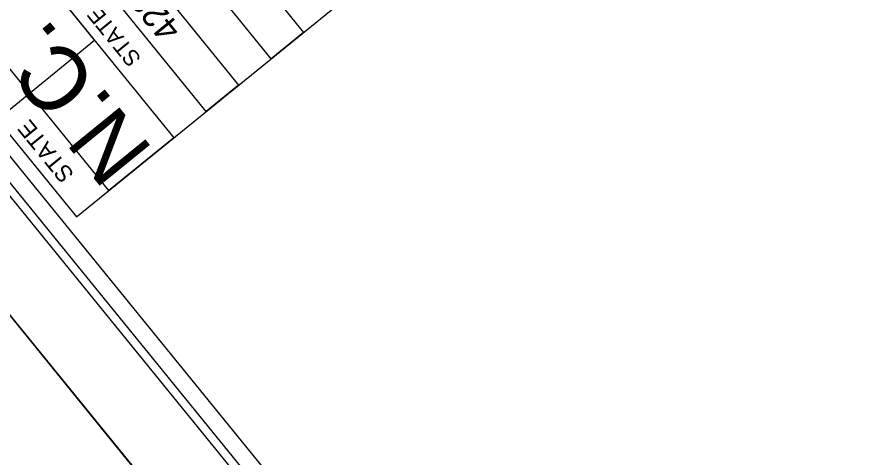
# Model space of a CAD drawing. Extents: x 2596486 to 2602076, y 851390 to 856110.
# Drawn here: x 2596823.3 to 2597258.5, y 853128.6 to 853352.8 of the extents above; entities that cross this region are included whole.
import ezdxf

# ---------------------------------------------------------------- set-up
doc = ezdxf.new("R2010")
doc.units = 0
for name, color, linetype in [('Sheet Cutting Line CELL', 7, 'Continuous'), ('Sheet Data Field CELL', 7, 'Continuous'), ('Sheet Plot Border Inside CELL', 7, 'Continuous'), ('Sheet Plot Border Outside CELL', 7, 'Continuous'), ('Sheet Title CELL', 7, 'Continuous')]:
    doc.layers.add(name, color=color, linetype=linetype)

msp = doc.modelspace()

# ---------------------------------------------------------------- linework, layer by layer
at = {"layer": 'Sheet Cutting Line CELL'}
msp.add_line((2598291.52, 851390.23), (2596485.91, 853611.8), dxfattribs=at)
at = {"layer": 'Sheet Plot Border Inside CELL'}
msp.add_lwpolyline([(2599699.12, 852562.74), (2597912.27, 854761.23), (2596520.36, 853629.94), (2598307.2, 851431.45)], close=True, dxfattribs=at)
at = {"layer": 'Sheet Plot Border Outside CELL'}
msp.add_lwpolyline([(2596485.91, 853611.8), (2598291.52, 851390.23), (2599742.65, 852569.65), (2597937.05, 854791.22)], close=True, dxfattribs=at)
at = {"layer": 'Sheet Title CELL'}
for points in [[(2596674.06, 853707.76), (2596968.92, 853344.98), (2596952.45, 853331.59), (2596657.57, 853694.36)], [(2596641.1, 853680.97), (2596935.96, 853318.18), (2596919.47, 853304.78), (2596624.61, 853667.57)], [(2596608.1, 853654.15), (2596902.96, 853291.37), (2596869.98, 853264.56), (2596575.12, 853627.35)], [(2596558.63, 853613.94), (2596853.5, 853251.17), (2597051.37, 853411.99), (2596953.12, 853532.91), (2596804.71, 853412.29), (2596862.77, 853340.85), (2596813.28, 853300.63)], [(2596547.83, 853603.01), (2598134.72, 851650.5)], [(2596559.8, 853601.75), (2598082.33, 851728.47)]]:
    msp.add_lwpolyline(points, dxfattribs=at)

# ---------------------------------------------------------------- texts
at = {"layer": 'Sheet Data Field CELL'}
msp.add_text('42302.1.1 ', height=12.75, rotation=129.1028, dxfattribs=at).set_placement((2596907.31, 853346.83))
at = {"layer": 'Sheet Title CELL'}
for s, height, p in [('STATE PROJ. NO.', 8.16, (2596886.84, 853331.82)), ('N.C.', 32.895, (2596893.12, 853285.01)), ('STATE', 8.5, (2596852.72, 853272.99))]:
    msp.add_text(s, height=height, rotation=129.1028, dxfattribs=at).set_placement(p)

doc.saveas('drawing.dxf')
